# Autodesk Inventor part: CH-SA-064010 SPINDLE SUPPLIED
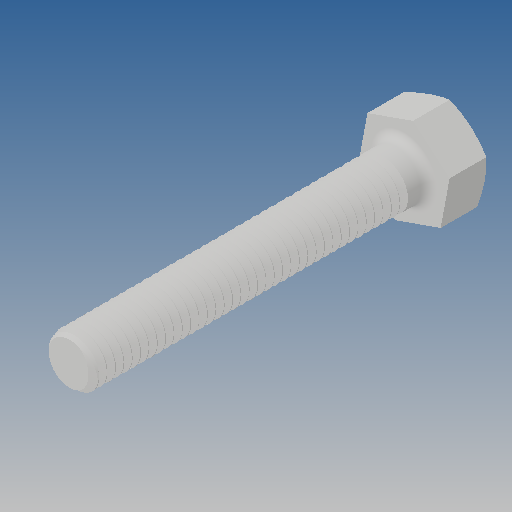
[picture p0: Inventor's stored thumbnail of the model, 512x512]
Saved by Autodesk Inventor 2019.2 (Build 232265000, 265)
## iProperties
Created: 2012-09
Part Number: CH-SA-064010 SPINDLE SUPPLIED
Material: Ogólny
Document SubType Name: Modeling
Designer: CADENGINEERING4
Density: 1 g/cm^3
Appearance: Domyślna
Author: CADENGINEERING4
Revision Number: ÈÎºÎ
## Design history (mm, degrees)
feature "ÇÐ³ý-É¨Ãè1"
node "Bryła1"
